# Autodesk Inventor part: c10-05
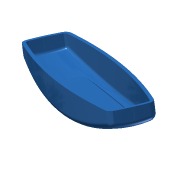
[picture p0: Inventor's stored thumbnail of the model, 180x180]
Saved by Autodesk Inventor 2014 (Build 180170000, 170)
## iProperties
Created: 2010-12
Part Number: c10-05
Material: Generic
Document SubType Name: Modeling
Designer: Thom Tremblay
Density: 1 g/cm^3
Appearance: Cyan
Author: Thom Tremblay
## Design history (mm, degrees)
sketch "Sketch1"
  geometry: L1 (-60, -12)-(60, -12); L2 (60, -12)-(60, 12); L3 (60, 12)-(-60, 12); L4 (-60, 12)-(-60, -12); A1 r 350 centre (0, -332.819) between (60, 12) and (-60, 12); A2 r 350 centre (0, 332.819) between (-60, -12) and (60, -12); 3 further points
  constraints: 8 end point, 4 point on circle, 2 centre point, 2 midpoint, 2 parallel, 1 equal radius, 1 horizontal, 1 horizontal alignment, 1 perpendicular, 1 vertical alignment
  dimensions: "d0" = 120 distance of L3.end L2.end; "d1" = 24 distance of L2.end L1.end; "d2" = 350 radius of A1
workplane "Work Plane4"
sketch "Sketch5"
  geometry: L1 (-60, 12)-(-60, -12) reference; L2 (60, -12)-(60, 12) reference; L3 (-58, 10.314)-(-58, -10.314); L4 (58, -10.314)-(58, 10.314); A1 r 350 centre (0, 332.819) between (-60, -12) and (60, -12) reference; A2 r 350 centre (0, -332.819) between (60, 12) and (-60, 12) reference; A3 r 348 centre (0, 332.819) between (-58, -10.314) and (58, -10.314); A4 r 348 centre (0, -332.819) between (58, 10.314) and (-58, 10.314); 1 further point
  constraints: 4 end point, 4 point on circle, 2 centre point, 3 other
  dimensions: "d37" = 2 distance between parallel lines of L2 L4
sketch "Sketch6"
  geometry: L1 (-60, 0)-(60, 0); L2 (60, 0)-(58.843, 22.085); L3 (-60, 0)-(-58.779, 23.307); A1 r 691.758 centre (630.81, -36.204) between (-60, 0) and (-58, -100); A2 r 691.758 centre (-630.81, -36.204) between (58, -100) and (60, 0); 1 further point
  constraints: 6 end point, 4 point on circle, 2 centre point, 2 tangent, 1 horizontal
  dimensions: "d53" = 87 deg angle of L1 L3; "d54" = 87 deg angle of L1 L2 (= d53)
sketch "Sketch7"
  geometry: L1 (17.181, 0)-(12, 0) reference; L2 (15.181, -100)-(10.314, -100) reference; L3 (17.181, 0)-(16.768, 11.838); A1 r 911.322 centre (-893.585, -31.805) between (15.181, -100) and (17.181, 0); 1 further point
  constraints: 2 end point, 2 point on circle, 1 centre point, 1 tangent
  dimensions: "d56" = 88 deg angle of L1 L3
feature "LoftSrf2" sketch "Sketch5", "Sketch6", "Sketch7" dims "d57" = 0, "d58" = 90 deg, "d59" = 0, "d60" = 90 deg, "d61" = 0, "d62" = 90 deg, "d63" = 0, "d64" = 90 deg, "d65" = 0, "d66" = 90 deg
sketch "Sketch2"
  geometry: L1 (-75, -16)-(75, -16); L2 (-75, -60)-(75, -60); A1 r 183.781 centre (0, -183.781) between (75, -16) and (-75, -16); 2 further points
  constraints: 4 end point, 3 point on circle, 1 centre point, 1 coincident, 1 horizontal, 1 parallel
  dimensions: "d5" = 16 distance from line of point (0, 0) L1; "d7" = 60 distance from line of point (0, 0) L2; "d55" = 150 distance of L1.start L1.end
feature "RevolutionSrf1" sketch "Sketch2" dims angle "d8" = 40 deg
patch "Boundary Patch1" dims "d13" = 0, "d67" = 0, "d68" = 0, "d69" = 0, "d70" = 0
workplane "Work Plane1"
sketch "Sketch3"
  geometry: L1 (52, -85)-(52, -73); L2 (38, -73)-(38, -85); A1 r 7 centre (45, -73) between (52, -73) and (38, -73); A2 r 7 centre (45, -85) between (38, -85) and (52, -85); 1 further point
  constraints: 4 end point, 4 point on circle, 4 tangent, 2 centre point, 1 parallel, 1 vertical
  dimensions: "d15" = 12 distance of L1.start L1.end; "d16" = 7 radius of A1; "d50" = 45 horizontal distance of A1.centre point (0, 0); "d51" = 85 vertical distance of point (0, 0) A2.centre
extrude_surface "ExtrusionSrf2" sketch "Sketch3" dims "d19" = 14, "d20" = 5 deg
pattern_linear "Rectangular Pattern1" dims "d23" = 90
workplane "Work Plane2"
feature "Sculpt1"
sketch "Sketch4"
  geometry: L1 (-24.5, 6)-(24.5, 6); L2 (27.5, 3)-(27.5, -3); L3 (24.5, -6)-(-24.5, -6); L4 (-27.5, -3)-(-27.5, 3); A1 r 3 centre (-24.5, 3) between (-24.5, 6) and (-27.5, 3); A2 r 3 centre (24.5, 3) between (27.5, 3) and (24.5, 6); A3 r 3 centre (24.5, -3) between (24.5, -6) and (27.5, -3); A4 r 3 centre (-24.5, -3) between (-27.5, -3) and (-24.5, -6); 6 further points
  constraints: 8 end point, 8 point on circle, 8 tangent, 6 point on line, 4 centre point, 3 equal radius, 2 midpoint, 2 parallel, 1 horizontal, 1 horizontal alignment, 1 perpendicular, 1 vertical alignment
  dimensions: "d28" = 55 distance of point (27.5, -6) point (-27.5, -6); "d29" = 12 distance of point (27.5, 6) point (27.5, -6); "d30" = 3 radius of A1
extrude_surface "ExtrusionSrf6" sketch "Sketch4" dims "d31" = 14, "d32" = 45 deg
patch "Boundary Patch2" dims "d33" = 0, "d34" = 0
fillet "Fillet1" dims "d79" = 4, "d80" = 3, "d81" = 1
feature "Sculpt2"
node "Splitting Plane 1"
shell "Shell1" dims "d83" = 2
split "Split1"
  body "Solid1"
body "Srf2"
body "Srf3"
body "Srf4"
body "Srf5"
body "Srf6"
body "Srf7"
body "Srf8"
body "Srf9"
body "Srf11"
feature "Stitch Surface1"
body "Srf12"
extrude_surface "ExtrusionSrf3"
extrude_surface "ExtrusionSrf4"
extrude_surface "ExtrusionSrf5"
node "Front"
node "Back"
other parameters: "d14" = -24, "d52" = -6
